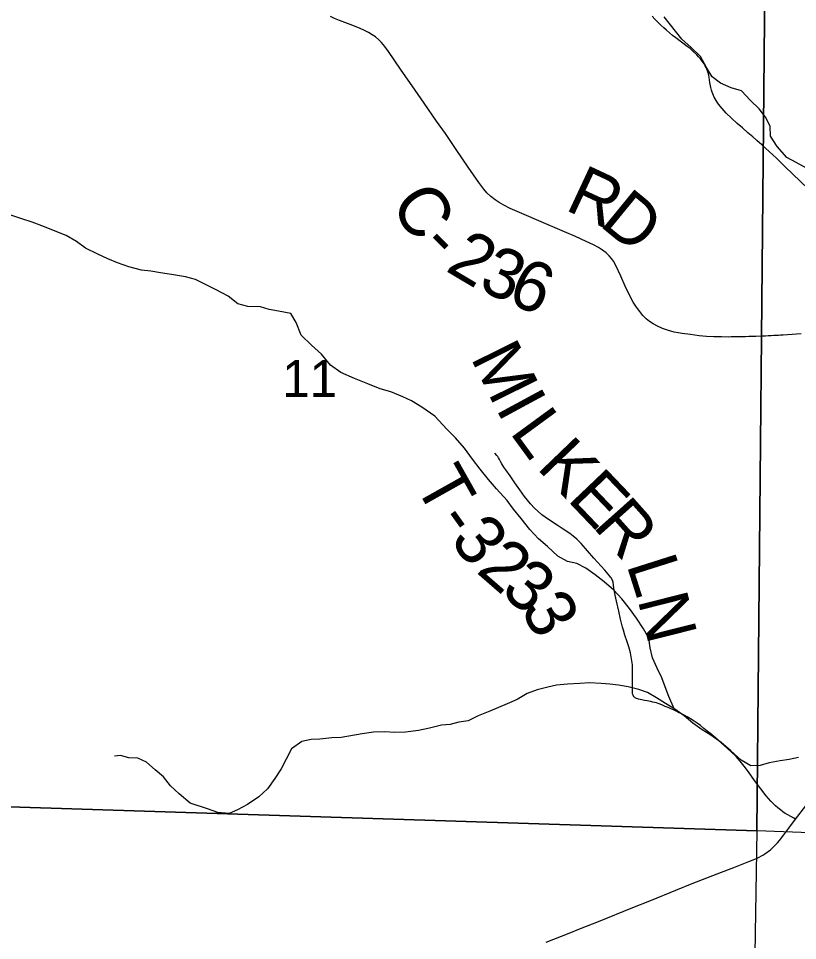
# Model space of a CAD drawing. Extents: x 0 to 34, y 0 to 22.
# Drawn here: x 25.255 to 26.138, y 18.613 to 19.658 of the extents above; entities that cross this region are included whole.
import ezdxf

# ---------------------------------------------------------------- set-up
doc = ezdxf.new("R2010")
doc.units = 0
for name, color, linetype in [('GM_X_Corporation', 7, 'Continuous'), ('GM_X_County_Road', 7, 'Continuous'), ('GM_X_County_Road_Text', 7, 'Continuous'), ('GM_X_Minor_River', 7, 'Continuous'), ('GM_X_Section_Text', 7, 'Continuous'), ('GM_X_Township_Road', 7, 'Continuous'), ('GM_X_Township_Road_Text', 7, 'Continuous')]:
    doc.layers.add(name, color=color, linetype=linetype)

msp = doc.modelspace()

# ---------------------------------------------------------------- linework, layer by layer
at = {"layer": 'GM_X_Corporation'}
for points in [[(25.0844, 19.7972), (26.1009, 19.7362), (26.0916, 18.7368), (25.0685, 18.7697)], [(27.1321, 19.6957), (27.1305, 19.6616), (27.1072, 18.6988), (26.0916, 18.7368), (26.1009, 19.7362)], [(26.0916, 18.7368), (26.075, 17.7146), (25.0591, 17.7438), (25.0685, 18.7697)]]:
    msp.add_lwpolyline(points, close=True, dxfattribs=at)
at = {"layer": 'GM_X_County_Road'}
for points in [[(26.1417, 19.3003), (26.1364, 19.2998), (26.1316, 19.2994), (26.1262, 19.299), (26.1213, 19.2987), (26.1184, 19.2985), (26.116, 19.2984), (26.1118, 19.2982), (26.1107, 19.2981), (26.1078, 19.298), (26.1061, 19.2979), (26.1043, 19.2978), (26.1014, 19.2976), (26.0971, 19.2975), (26.0904, 19.2972), (26.088, 19.2971), (26.0862, 19.2971), (26.0837, 19.297), (26.0825, 19.297), (26.0788, 19.2969), (26.0764, 19.2968), (26.0733, 19.2967), (26.0703, 19.2967), (26.0667, 19.2966), (26.0625, 19.2966), (26.0591, 19.2965), (26.0514, 19.2966), (26.043, 19.2969), (26.0346, 19.2973), (26.0261, 19.298), (26.0164, 19.2992), (26.0072, 19.3005), (25.9981, 19.3022), (25.9916, 19.3039), (25.9846, 19.3062), (25.979, 19.3087), (25.9742, 19.3113), (25.9702, 19.3141), (25.9664, 19.3172), (25.9625, 19.3211), (25.9589, 19.3253), (25.9553, 19.3302), (25.9517, 19.336), (25.9473, 19.3441), (25.9424, 19.3542), (25.9374, 19.3655), (25.9319, 19.3774), (25.9291, 19.3824), (25.927, 19.3855), (25.9245, 19.3884), (25.9209, 19.3919), (25.9169, 19.395), (25.9122, 19.398), (25.9067, 19.401), (25.8982, 19.4049), (25.8863, 19.4103), (25.8737, 19.4156), (25.8446, 19.4282), (25.828, 19.4353), (25.8122, 19.4423), (25.805, 19.4459), (25.7996, 19.4489), (25.7951, 19.452), (25.7903, 19.4558), (25.7859, 19.4601), (25.7822, 19.4642), (25.7767, 19.4716), (25.7646, 19.4889), (25.7509, 19.5089), (25.7388, 19.527), (25.7288, 19.5412), (25.7146, 19.5616), (25.7012, 19.581), (25.6888, 19.5989), (25.6808, 19.6107), (25.6745, 19.6199), (25.6701, 19.6259), (25.6664, 19.6302), (25.6634, 19.6333), (25.6596, 19.6366), (25.656, 19.6391), (25.6517, 19.6418), (25.6455, 19.6448), (25.6398, 19.6473), (25.631, 19.6505), (25.6188, 19.6551), (25.6131, 19.6574), (25.6088, 19.6597)], [(26.1499, 19.4643), (26.1233, 19.4897), (26.1137, 19.4992), (26.1055, 19.5069), (26.0972, 19.5143), (26.0916, 19.5192), (26.0869, 19.5233), (26.0813, 19.5281), (26.0752, 19.5334), (26.0692, 19.5386), (26.063, 19.5444), (26.057, 19.5502), (26.0523, 19.5554), (26.0483, 19.5603), (26.0467, 19.5625), (26.0454, 19.5645), (26.0443, 19.5665), (26.0433, 19.5683), (26.0424, 19.5702), (26.0416, 19.5721), (26.0409, 19.5741), (26.0402, 19.5764), (26.0396, 19.5792), (26.0385, 19.585), (26.0376, 19.5909), (26.0371, 19.5932), (26.0365, 19.5958), (26.0358, 19.598), (26.035, 19.5999), (26.0341, 19.602), (26.0332, 19.6039), (26.0322, 19.6058), (26.0308, 19.6077), (26.0278, 19.6117), (26.0257, 19.6141), (26.0236, 19.6163), (26.019, 19.6206), (26.016, 19.6233), (26.0128, 19.6258), (25.9998, 19.6354), (25.996, 19.6384), (25.9926, 19.6412), (25.9893, 19.6441), (25.9861, 19.6469), (25.9829, 19.65), (25.9795, 19.6534), (25.9761, 19.6569), (25.9732, 19.6601)], [(26.1354, 18.7502), (26.147, 18.7651)], [(25.853, 18.6107), (25.879, 18.6209), (25.8899, 18.6253), (25.9142, 18.6349), (25.9494, 18.6491), (25.9724, 18.6584), (26, 18.6697), (26.0184, 18.6771), (26.0468, 18.6881), (26.0676, 18.6962), (26.0827, 18.702), (26.0876, 18.704), (26.0919, 18.706), (26.0944, 18.7072), (26.0969, 18.7086), (26.0991, 18.7099), (26.1012, 18.7112), (26.103, 18.7124), (26.1048, 18.7137), (26.1066, 18.7151), (26.1086, 18.7168), (26.1106, 18.7187), (26.1127, 18.7209), (26.115, 18.7235), (26.1173, 18.7261), (26.1223, 18.7325), (26.1279, 18.7399), (26.1354, 18.7502)]]:
    msp.add_lwpolyline(points, dxfattribs=at)
at = {"layer": 'GM_X_Minor_River'}
for points in [[(26.0344, 19.602), (26.0279, 19.6144), (26.0172, 19.6245), (26.0065, 19.6339), (25.9867, 19.6594)], [(26.1477, 19.488), (26.1363, 19.4943), (26.1256, 19.4999), (26.1146, 19.5126), (26.1069, 19.5243), (26.1068, 19.5353), (26.1014, 19.5455), (26.0942, 19.5552), (26.0843, 19.5646), (26.0743, 19.5755), (26.0626, 19.5788), (26.0504, 19.5843), (26.0409, 19.5914), (26.0344, 19.602)], [(25.9981, 18.8753), (25.9919, 18.8892), (25.9876, 18.9002), (25.9841, 18.9104), (25.9787, 18.9213), (25.9733, 18.933), (25.9706, 18.9443), (25.9694, 18.9553), (25.9632, 18.9659), (25.9552, 18.9779), (25.9475, 18.9888), (25.9387, 18.9997), (25.9296, 19.0098), (25.9185, 19.0192), (25.9083, 19.027), (25.898, 19.0345), (25.8877, 19.0397), (25.8771, 19.0422), (25.8661, 19.0482), (25.8543, 19.0591), (25.8444, 19.068), (25.8345, 19.0785), (25.8245, 19.0909), (25.8161, 19.1015), (25.8089, 19.1112), (25.7966, 19.1244), (25.7875, 19.1349), (25.7783, 19.1469), (25.7695, 19.1582), (25.7603, 19.1706), (25.7504, 19.1822), (25.7405, 19.192), (25.7267, 19.207), (25.7123, 19.2171), (25.7005, 19.2241), (25.6906, 19.2286), (25.677, 19.2345), (25.6649, 19.2378), (25.6508, 19.2433), (25.636, 19.2496), (25.6205, 19.2563), (25.6087, 19.2645), (25.5984, 19.2772), (25.5873, 19.2874), (25.5755, 19.2986), (25.5697, 19.3129), (25.5636, 19.3231), (25.5496, 19.326), (25.539, 19.3278), (25.5295, 19.3307), (25.5151, 19.3313), (25.5037, 19.3342), (25.4927, 19.3428), (25.479, 19.3499), (25.4684, 19.3551), (25.4559, 19.3618), (25.4445, 19.3647), (25.4286, 19.3675), (25.4161, 19.3693), (25.4051, 19.3711), (25.3945, 19.3721), (25.3801, 19.3761), (25.3673, 19.3805), (25.3566, 19.3853), (25.3452, 19.3905), (25.3312, 19.3972), (25.3209, 19.4047), (25.3091, 19.4114), (25.2966, 19.4165), (25.2845, 19.4213), (25.2708, 19.4265), (25.2591, 19.4305), (25.2466, 19.4346)], [(26.1388, 18.8199), (26.1282, 18.8176), (26.118, 18.8163), (26.1055, 18.8139), (26.0954, 18.8108), (26.0848, 18.8107), (26.0738, 18.817), (26.0623, 18.8275), (26.0513, 18.8372), (26.0395, 18.8454), (26.0296, 18.8514), (26.019, 18.8588), (26.0094, 18.8671), (25.9988, 18.8749), (25.9881, 18.8813), (25.9779, 18.8876), (25.9676, 18.8935), (25.9578, 18.8969), (25.946, 18.9001), (25.935, 18.9019), (25.9252, 18.9033), (25.9154, 18.904), (25.9021, 18.9046), (25.8912, 18.9037), (25.8772, 18.9032), (25.8647, 18.9019), (25.8549, 18.8996), (25.8429, 18.8968), (25.8316, 18.8925), (25.8203, 18.8859), (25.8086, 18.8809), (25.7988, 18.8766), (25.789, 18.8727), (25.7758, 18.8673), (25.7645, 18.8615), (25.754, 18.8602), (25.7442, 18.8575), (25.7343, 18.8566), (25.7208, 18.8534), (25.7083, 18.8507), (25.6936, 18.8486), (25.6815, 18.8485), (25.6698, 18.8491), (25.6573, 18.8486), (25.6445, 18.847), (25.6207, 18.8425), (25.6101, 18.8424), (25.5965, 18.8408), (25.5867, 18.8403), (25.5761, 18.8383), (25.5645, 18.8298), (25.5585, 18.818), (25.5529, 18.807), (25.5455, 18.7963), (25.5373, 18.7845)], [(25.5373, 18.7845), (25.5275, 18.7753), (25.5147, 18.7668), (25.5034, 18.7606), (25.4937, 18.7567), (25.4812, 18.7577), (25.4694, 18.7618), (25.4497, 18.7684), (25.4371, 18.7789), (25.4276, 18.7879), (25.4196, 18.798), (25.4101, 18.8059), (25.4002, 18.8149), (25.3903, 18.8193), (25.3801, 18.8196), (25.3706, 18.8221), (25.3638, 18.8217)]]:
    msp.add_lwpolyline(points, dxfattribs=at)
at = {"layer": 'GM_X_Township_Road'}
msp.add_lwpolyline([(26.1354, 18.7502), (26.1334, 18.7512), (26.13, 18.7531), (26.1266, 18.7549), (26.1238, 18.7566), (26.121, 18.7585), (26.1184, 18.7606), (26.1154, 18.7629), (26.1129, 18.7653), (26.1101, 18.768), (26.1075, 18.7707), (26.1021, 18.7767), (26.096, 18.7845), (26.0891, 18.7941), (26.0822, 18.8038), (26.0774, 18.8102), (26.0726, 18.816), (26.0681, 18.821), (26.0623, 18.8267), (26.0545, 18.8338), (26.0451, 18.8419), (26.0395, 18.8467), (26.0355, 18.85), (26.0317, 18.853), (26.0278, 18.8561), (26.024, 18.8588), (26.0205, 18.8611), (26.0166, 18.8637), (26.0127, 18.866), (26.0091, 18.868), (26.0054, 18.87), (26.0029, 18.8712), (26.0001, 18.8726), (25.9971, 18.8739), (25.9941, 18.8753), (25.991, 18.8766), (25.9878, 18.878), (25.9846, 18.8793), (25.9821, 18.8804), (25.9798, 18.8812), (25.9778, 18.8819), (25.9758, 18.8824), (25.9737, 18.8829), (25.9716, 18.8834), (25.9693, 18.8838), (25.9673, 18.8841), (25.9643, 18.8846), (25.9612, 18.8852), (25.9593, 18.8856), (25.9576, 18.886), (25.9564, 18.8864), (25.9554, 18.8868), (25.9545, 18.8873), (25.9538, 18.8877), (25.953, 18.8883), (25.9524, 18.8889), (25.9518, 18.8897), (25.9514, 18.8905), (25.9511, 18.8914), (25.9509, 18.8923), (25.9507, 18.8934), (25.9506, 18.8948), (25.9507, 18.9029), (25.9509, 18.9115), (25.9509, 18.9202), (25.9508, 18.9227), (25.9506, 18.9252), (25.9498, 18.932), (25.9485, 18.9387), (25.9467, 18.9453), (25.9448, 18.9512), (25.9422, 18.9588), (25.9406, 18.9642), (25.9396, 18.9678), (25.9373, 18.9768), (25.9352, 18.9858), (25.9328, 18.9973), (25.9313, 19.004), (25.9303, 19.0083), (25.9296, 19.0119), (25.9291, 19.0152), (25.9287, 19.0186), (25.9284, 19.0199), (25.928, 19.021), (25.9275, 19.0222), (25.9269, 19.0232), (25.926, 19.0244), (25.925, 19.0257), (25.9194, 19.0323), (25.9069, 19.0461), (25.8926, 19.0625), (25.8878, 19.0674), (25.8835, 19.071), (25.8796, 19.074), (25.8724, 19.0789), (25.8656, 19.0832), (25.8557, 19.0897), (25.8481, 19.0951), (25.8434, 19.0991), (25.8398, 19.1025), (25.8352, 19.1075), (25.8286, 19.1158), (25.8231, 19.1233), (25.8173, 19.1314), (25.812, 19.1391), (25.8071, 19.1462), (25.805, 19.1492), (25.8028, 19.1529), (25.8013, 19.1556), (25.8002, 19.1577), (25.799, 19.1598), (25.7981, 19.161), (25.7972, 19.1622), (25.7949, 19.1649)], dxfattribs=at)

# ---------------------------------------------------------------- texts
at = {"layer": 'GM_X_County_Road_Text'}
for s, rotation, p in [('R', 334.9903, (25.8729, 19.4413)), ('C', 303.3534, (25.6754, 19.447)), ('D', 320.6902, (25.9121, 19.4236)), ('-', 315.0444, (25.709, 19.3982)), ('2', 329.229, (25.7376, 19.3723)), ('3', 336.2718, (25.7745, 19.3509)), ('6', 336.6674, (25.8069, 19.3367))]:
    msp.add_text(s, height=0.0568, rotation=rotation, dxfattribs=at).set_placement(p)
at = {"layer": 'GM_X_Section_Text'}
msp.add_text('11', height=0.04186, rotation=0, dxfattribs=at).set_placement((25.554, 19.2286))
at = {"layer": 'GM_X_Township_Road_Text'}
for s, rotation, p in [('M', 296.4416, (25.7668, 19.2733)), ('I', 298.409, (25.7952, 19.2162)), ('L', 306.2023, (25.8108, 19.1887)), ('K', 313.8966, (25.8411, 19.1482)), ('T', 299.3462, (25.703, 19.1303)), ('E', 313.668, (25.8757, 19.1122)), ('R', 311.6767, (25.9047, 19.0818)), ('-', 305.5239, (25.7274, 19.0876)), ('3', 308.6235, (25.7429, 19.0659)), ('2', 318.9899, (25.7725, 19.0305)), ('L', 287.6293, (25.9437, 19.0388)), ('3', 320.0967, (25.7999, 19.0068)), ('3', 298.8754, (25.8232, 18.9886)), ('N', 284.1007, (25.9563, 18.9992))]:
    msp.add_text(s, height=0.0568, rotation=rotation, dxfattribs=at).set_placement(p)

doc.saveas('drawing.dxf')
